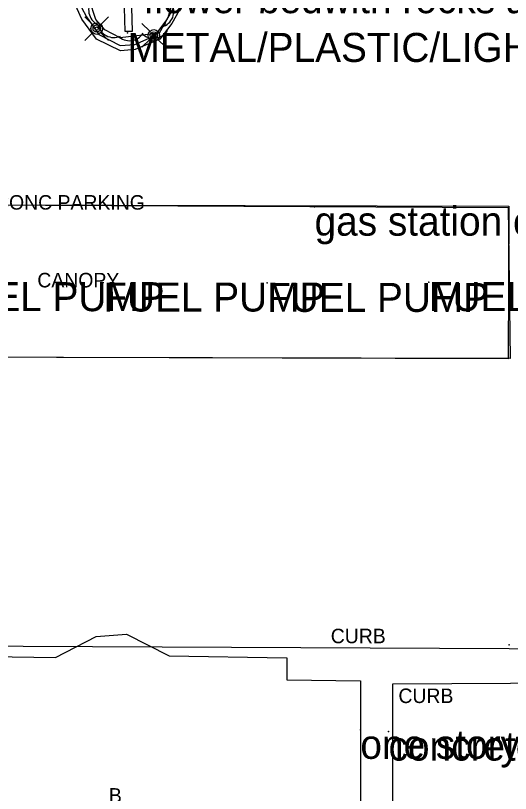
# Model space of a CAD drawing. Extents: x 1802180 to 1804859, y 572524 to 575172.
# Drawn here: x 1803724.4 to 1803809.7, y 573582.9 to 573717 of the extents above; entities that cross this region are included whole.
import ezdxf

# ---------------------------------------------------------------- set-up
doc = ezdxf.new("R2010")
doc.units = 0
for name, color, linetype in [('S_BUILDING', 7, 'Continuous'), ('S_BUILDING_ANNOT', 7, 'Continuous'), ('S_CURB', 7, 'Continuous'), ('S_CURB_ANNOT', 7, 'Continuous'), ('S_MISC_STRUCTURES', 7, 'Continuous'), ('S_MISC_STRUCTURES_ANNOT', 7, 'Continuous'), ('S_MSC_PT_SYM', 7, 'Continuous'), ('S_PARKING', 7, 'Continuous'), ('S_PARKING_ANNOT', 7, 'Continuous'), ('S_SIGN', 7, 'Continuous'), ('S_SIGN_ANNOT', 7, 'Continuous'), ('S_SPRINKLER_HEAD', 7, 'Continuous'), ('S_SURVEY_TEXT_ANNOT', 7, 'Continuous'), ('S_TREE', 7, 'Continuous')]:
    doc.layers.add(name, color=color, linetype=linetype)

msp = doc.modelspace()

# ---------------------------------------------------------------- linework, layer by layer
at = {"layer": 'S_BUILDING'}
msp.add_lwpolyline([(1803783.86, 573550.47), (1803698.78, 573550.9), (1803698.98, 573602.8), (1803708.84, 573602.75), (1803708.79, 573606.66), (1803731.22, 573606.3), (1803738.28, 573609.94), (1803743.5, 573610.3), (1803750.85, 573606.56), (1803771.09, 573606.24), (1803771.14, 573602.45), (1803783.83, 573602.26), (1803783.86, 573550.47)], dxfattribs=at)
at = {"layer": 'S_CURB'}
msp.add_lwpolyline([(1803734.62, 573722.43), (1803735.41, 573719.52), (1803735.75, 573718.35), (1803736.57, 573716.76), (1803738.74, 573713.7), (1803742.42, 573711.82), (1803744.94, 573711.94), (1803748.4, 573713.52), (1803750.46, 573716.24), (1803751.49, 573718), (1803752.22, 573722.06)], dxfattribs=at)
at = {"layer": 'S_MISC_STRUCTURES'}
msp.add_lwpolyline([(1803673.04, 573684.47), (1803809.37, 573684.09), (1803809.29, 573657.76), (1803672.92, 573658.17), (1803673.04, 573684.47)], dxfattribs=at)
at = {"layer": 'S_MSC_PT_SYM'}
for points in [[(1803743.67, 573713.96), (1803743.67, 573714.01), (1803743.67, 573713.96), (1803743.62, 573713.96), (1803743.67, 573713.96), (1803743.67, 573713.91), (1803743.67, 573713.96), (1803743.72, 573713.96)], [(1803775.9, 573684.01), (1803775.9, 573684.06), (1803775.9, 573684.01), (1803775.85, 573684.01), (1803775.9, 573684.01), (1803775.9, 573683.96), (1803775.9, 573684.01), (1803775.95, 573684.01)], [(1803739.49, 573670.94), (1803739.49, 573670.99), (1803739.49, 573670.94), (1803739.44, 573670.94), (1803739.49, 573670.94), (1803739.49, 573670.89), (1803739.49, 573670.94), (1803739.54, 573670.94)], [(1803767.71, 573670.87), (1803767.71, 573670.92), (1803767.71, 573670.87), (1803767.66, 573670.87), (1803767.71, 573670.87), (1803767.71, 573670.82), (1803767.71, 573670.87), (1803767.76, 573670.87)], [(1803795.59, 573671.01), (1803795.59, 573671.06), (1803795.59, 573671.01), (1803795.54, 573671.01), (1803795.59, 573671.01), (1803795.59, 573670.96), (1803795.59, 573671.01), (1803795.64, 573671.01)], [(1803809.41, 573608.47), (1803809.41, 573608.52), (1803809.41, 573608.47), (1803809.36, 573608.47), (1803809.41, 573608.47), (1803809.41, 573608.42), (1803809.41, 573608.47), (1803809.46, 573608.47)], [(1803783.79, 573593.83), (1803783.79, 573593.88), (1803783.79, 573593.83), (1803783.74, 573593.83), (1803783.79, 573593.83), (1803783.79, 573593.78), (1803783.79, 573593.83), (1803783.84, 573593.83)], [(1803788.65, 573593.53), (1803788.65, 573593.58), (1803788.65, 573593.53), (1803788.6, 573593.53), (1803788.65, 573593.53), (1803788.65, 573593.48), (1803788.65, 573593.53), (1803788.7, 573593.53)]]:
    msp.add_lwpolyline(points, dxfattribs=at)
at = {"layer": 'S_PARKING'}
for points in [[(1803752.77, 573720.94), (1803752.57, 573717.81), (1803751.31, 573715.59), (1803749.22, 573712.89), (1803744.96, 573711.13), (1803742.43, 573710.89), (1803738.32, 573712.87), (1803735.79, 573716.34), (1803734.96, 573718.12), (1803734.66, 573719.3), (1803733.8, 573721.64), (1803734.26, 573722.73)], [(1803752.57, 573717.81), (1803751.31, 573715.59), (1803749.22, 573712.89), (1803744.96, 573711.13), (1803742.43, 573710.89), (1803738.32, 573712.87), (1803735.79, 573716.34), (1803734.96, 573718.12)], [(1803695.27, 573684.43), (1803809.28, 573683.84), (1803809.62, 573657.82), (1803706.96, 573658.08)], [(1803833.33, 573629.06), (1803833.33, 573607.69), (1803713.66, 573608.23)], [(1803789.37, 573551.02), (1803789.36, 573601.75), (1803840.12, 573602.03)]]:
    msp.add_lwpolyline(points, dxfattribs=at)
at = {"layer": 'S_SIGN'}
msp.add_lwpolyline([(1803744.22, 573722.6), (1803744.45, 573714.23), (1803743.24, 573714.21), (1803743.03, 573722.52), (1803744.22, 573722.6)], dxfattribs=at)
at = {"layer": 'S_SPRINKLER_HEAD'}
for p, q in [((1803737.65, 573715.41), (1803736.3, 573716.75)), ((1803739.05, 573715.41), (1803740.39, 573716.75)), ((1803747.49, 573714.24), (1803746.15, 573715.58)), ((1803748.9, 573714.24), (1803750.24, 573715.58)), ((1803737.65, 573714), (1803736.3, 573712.66)), ((1803739.05, 573714), (1803740.39, 573712.66)), ((1803747.49, 573712.83), (1803746.15, 573711.49)), ((1803748.9, 573712.83), (1803750.24, 573711.49))]:
    msp.add_line(p, q, dxfattribs=at)
for centre, radius in [((1803738.35, 573714.71), 0.994), ((1803738.35, 573714.71), 0.634), ((1803738.35, 573714.71), 0.274), ((1803748.19, 573713.53), 0.994), ((1803748.19, 573713.53), 0.634), ((1803748.19, 573713.53), 0.274)]:
    msp.add_circle(centre, radius, dxfattribs=at)
at = {"layer": 'S_TREE'}
msp.add_lwpolyline([(1803737.79, 573723.61), (1803748.81, 573723.59), (1803751.1, 573722.32), (1803751.47, 573719.6), (1803750.62, 573716.58), (1803749.13, 573713.9), (1803742.37, 573713.13), (1803739.74, 573714.49), (1803738.18, 573716.29), (1803737.12, 573719.64), (1803737.79, 573723.61)], dxfattribs=at)
for centre, start, end in [((1803739.81, 573717.93), 146.6596, 248.2565), ((1803748.8, 573717.71), 293.6114, 35.2083), ((1803741.31, 573716.02), 191.8758, 293.4727), ((1803748.14, 573715.89), 225.7368, 327.3337), ((1803743.98, 573715.47), 225.7368, 327.3337)]:
    msp.add_arc(centre, 2.85, start, end, dxfattribs=at)

# ---------------------------------------------------------------- texts
at = {"layer": 'S_BUILDING_ANNOT'}
msp.add_text('B', height=2.5, dxfattribs=at).set_placement((1803740.45, 573581.28))
at = {"layer": 'S_CURB_ANNOT'}
for p in [(1803778.69, 573608.76), (1803790.35, 573598.45)]:
    msp.add_text('CURB', height=2.5, dxfattribs=at).set_placement(p)
at = {"layer": 'S_MISC_STRUCTURES_ANNOT'}
msp.add_text('CANOPY', height=2.5, dxfattribs=at).set_placement((1803728.12, 573670.1))
at = {"layer": 'S_PARKING_ANNOT'}
msp.add_text('CONC PARKING', height=2.5, dxfattribs=at).set_placement((1803720.83, 573683.5))
at = {"layer": 'S_SIGN_ANNOT'}
msp.add_text('METAL/PLASTIC/LIGHTED EXXON JORDANS  ', height=5, dxfattribs=at).set_placement((1803743.67, 573708.96))
at = {"layer": 'S_SPRINKLER_HEAD'}
for p in [(1803738.3, 573714.66), (1803748.15, 573713.48)]:
    msp.add_text('+', height=0.1, dxfattribs=at).set_placement(p)
at = {"layer": 'S_SURVEY_TEXT_ANNOT'}
for s, p in [('flower bedwith rocks and sign', (1803746.44, 573717.36)), ('gas station canopy', (1803775.9, 573679.01)), ('FUEL PUMP ', (1803711.79, 573666)), ('FUEL PUMP ', (1803739.49, 573665.94)), ('FUEL PUMP ', (1803767.71, 573665.87)), ('FUEL PUMP ', (1803795.59, 573666.01)), ('one story brick gas station', (1803783.79, 573588.83)), ('concrete sidewalk', (1803788.65, 573588.53))]:
    msp.add_text(s, height=5, dxfattribs=at).set_placement(p)

doc.saveas('drawing.dxf')
